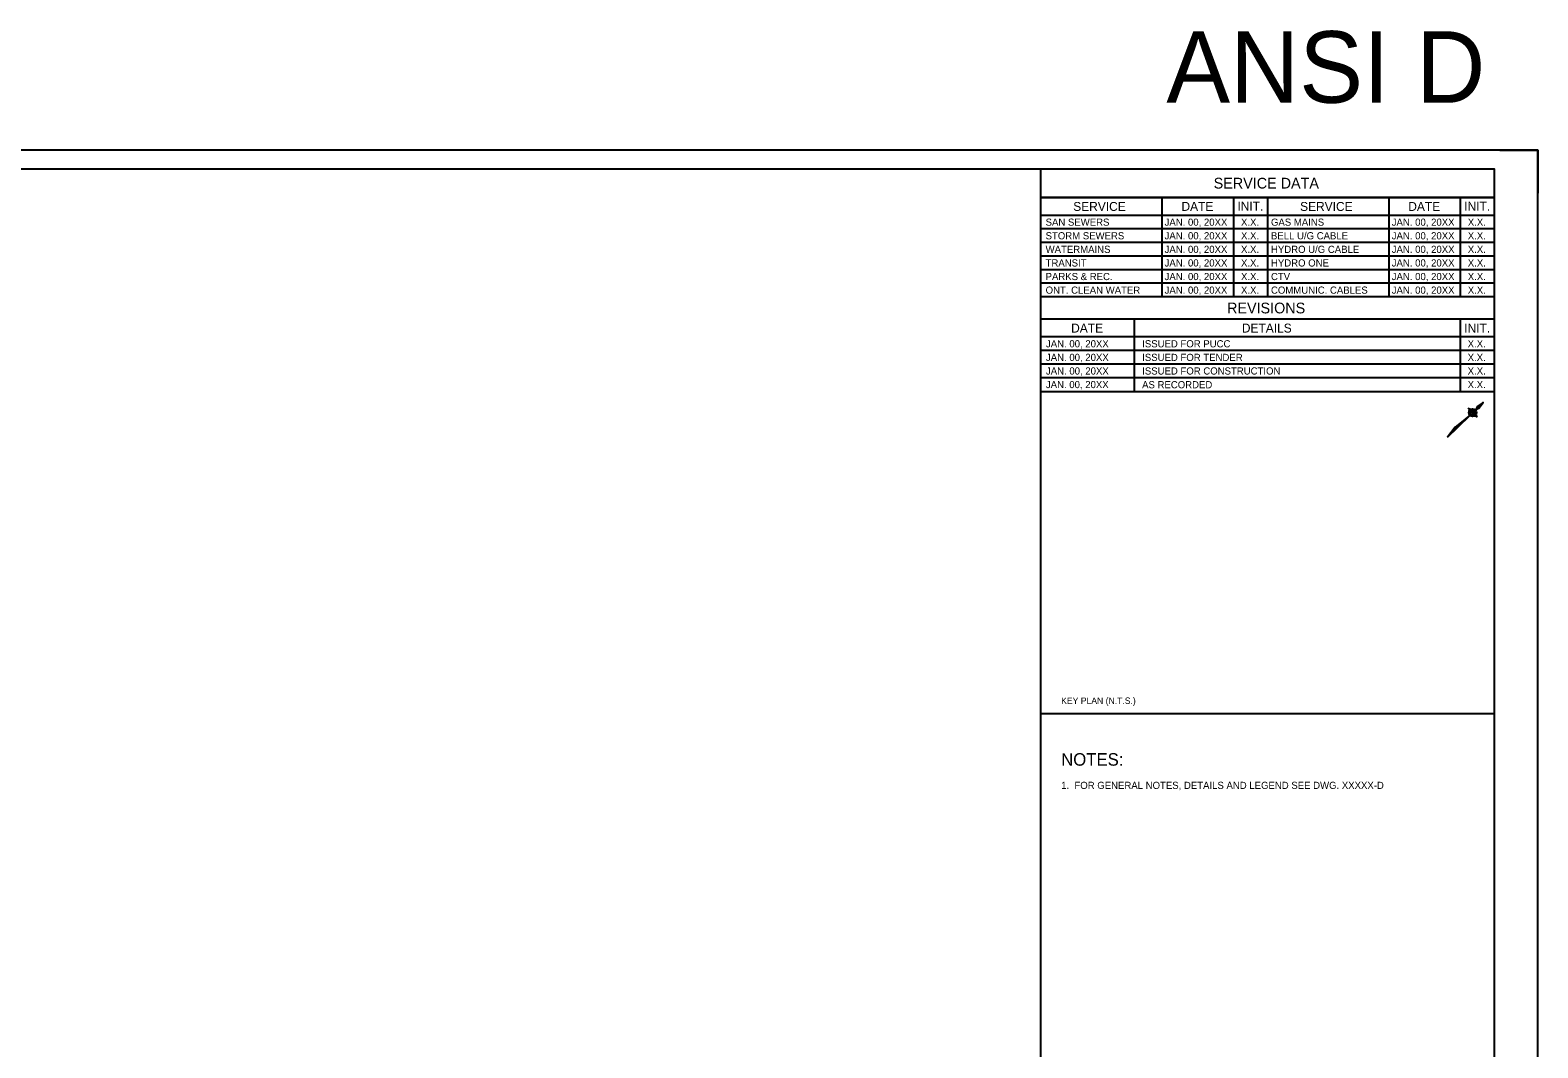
# Model space of a CAD drawing. Extents: x 613360 to 613780, y 4825621 to 4825911.
# Drawn here: x 613569.5 to 613780.3, y 4825769.2 to 4825911.5 of the extents above; entities that cross this region are included whole.
import ezdxf

# ---------------------------------------------------------------- set-up
doc = ezdxf.new("R2010")
doc.units = 0
for name, color, linetype in [('G-ANNO-KEYP', 7, 'Continuous'), ('G-ANNO-NPLT', 7, 'Continuous'), ('G-ANNO-TEXT', 7, 'Continuous'), ('G-ANNO-TTLB-TEXT', 7, 'Continuous'), ('G-TTLB-OTLN', 7, 'Continuous'), ('G-TTLB-OTLN-PB', 7, 'Continuous')]:
    doc.layers.add(name, color=color, linetype=linetype)

msp = doc.modelspace()

# ---------------------------------------------------------------- linework, layer by layer
at = {"layer": 'G-ANNO-KEYP'}
for p, q in [((613770.76, 4825857.62), (613767.64, 4825854.56)), ((613767.74, 4825854.69), (613770.74, 4825857.6)), ((613770.76, 4825857.62), (613768.73, 4825855.97)), ((613770.77, 4825858.38), (613770.51, 4825858.64)), ((613770.56, 4825858.46), (613770.71, 4825858.31)), ((613770.68, 4825858.07), (613770.78, 4825858.17)), ((613770.68, 4825858.05), (613770.76, 4825858.13)), ((613770.68, 4825858.03), (613770.76, 4825858.11)), ((613770.68, 4825858.01), (613770.75, 4825858.08)), ((613770.68, 4825857.99), (613770.74, 4825858.06)), ((613770.68, 4825857.97), (613770.74, 4825858.04)), ((613770.68, 4825857.96), (613770.74, 4825858.02)), ((613770.68, 4825857.94), (613770.74, 4825858)), ((613770.68, 4825857.92), (613770.74, 4825857.98)), ((613770.68, 4825857.91), (613770.74, 4825857.96)), ((613770.69, 4825858.59), (613770.84, 4825858.44)), ((613770.69, 4825858.12), (613770.85, 4825858.28)), ((613770.69, 4825858.1), (613770.8, 4825858.2)), ((613770.69, 4825857.89), (613770.74, 4825857.94)), ((613770.69, 4825857.87), (613770.75, 4825857.93)), ((613770.7, 4825858.15), (613771.01, 4825858.44)), ((613770.7, 4825857.86), (613770.75, 4825857.91)), ((613770.7, 4825857.85), (613770.75, 4825857.9)), ((613770.71, 4825858.18), (613770.97, 4825858.43)), ((613770.71, 4825857.83), (613770.76, 4825857.88)), ((613770.71, 4825857.82), (613770.76, 4825857.87)), ((613770.72, 4825857.8), (613770.77, 4825857.85)), ((613770.72, 4825857.79), (613770.77, 4825857.84)), ((613770.73, 4825858.21), (613770.94, 4825858.42)), ((613770.73, 4825857.78), (613770.78, 4825857.82)), ((613770.74, 4825857.77), (613770.78, 4825857.81)), ((613770.74, 4825857.75), (613770.79, 4825857.8)), ((613770.75, 4825857.74), (613770.8, 4825857.79)), ((613770.76, 4825858.26), (613770.89, 4825858.39)), ((613770.76, 4825857.73), (613770.8, 4825857.78)), ((613770.77, 4825857.72), (613770.81, 4825857.76)), ((613770.77, 4825857.71), (613770.82, 4825857.75)), ((613770.78, 4825857.7), (613770.83, 4825857.74)), ((613770.79, 4825857.69), (613770.84, 4825857.73)), ((613770.8, 4825857.68), (613770.85, 4825857.72)), ((613770.81, 4825857.67), (613770.86, 4825857.71)), ((613770.82, 4825857.66), (613770.86, 4825857.7)), ((613770.83, 4825857.65), (613770.87, 4825857.69)), ((613770.84, 4825857.64), (613770.88, 4825857.68)), ((613770.85, 4825857.63), (613770.9, 4825857.67)), ((613770.86, 4825857.62), (613770.91, 4825857.67)), ((613770.87, 4825858.3), (613771.03, 4825858.45)), ((613770.87, 4825858.3), (613771.03, 4825858.45)), ((613770.87, 4825857.61), (613770.92, 4825857.66)), ((613770.88, 4825857.61), (613770.93, 4825857.65)), ((613771.16, 4825858.25), (613770.89, 4825857.99)), ((613770.89, 4825857.99), (613770.92, 4825857.96)), ((613770.89, 4825857.6), (613770.94, 4825857.64)), ((613770.91, 4825857.59), (613770.95, 4825857.64)), ((613770.92, 4825857.96), (613771.11, 4825858.14)), ((613770.92, 4825857.58), (613770.97, 4825857.63)), ((613770.93, 4825857.58), (613770.98, 4825857.62)), ((613770.94, 4825857.57), (613770.99, 4825857.62)), ((613770.95, 4825858.35), (613771.06, 4825858.46)), ((613770.96, 4825857.56), (613771.01, 4825857.61)), ((613770.97, 4825857.56), (613771.02, 4825857.61)), ((613770.98, 4825857.55), (613771.04, 4825857.6)), ((613770.99, 4825858.37), (613771.08, 4825858.46)), ((613771, 4825857.55), (613771.05, 4825857.6)), ((613771.01, 4825857.54), (613771.07, 4825857.6)), ((613771.02, 4825858.38), (613771.1, 4825858.46)), ((613771.03, 4825857.54), (613771.08, 4825857.59)), ((613771.04, 4825857.54), (613771.1, 4825857.59)), ((613771.05, 4825858.39), (613771.12, 4825858.46)), ((613771.06, 4825857.53), (613771.12, 4825857.59)), ((613771.07, 4825858.39), (613771.14, 4825858.47)), ((613771.08, 4825857.53), (613771.14, 4825857.59)), ((613771.09, 4825857.53), (613771.16, 4825857.59)), ((613771.1, 4825858.4), (613771.16, 4825858.46)), ((613771.11, 4825858.14), (613771.12, 4825857.75)), ((613771.11, 4825857.53), (613771.18, 4825857.59)), ((613771.12, 4825858.4), (613771.18, 4825858.46)), ((613771.12, 4825857.75), (613771.39, 4825858.02)), ((613771.13, 4825857.53), (613771.2, 4825857.59)), ((613771.14, 4825858.4), (613771.2, 4825858.46)), ((613771.15, 4825857.52), (613771.22, 4825857.6)), ((613771.16, 4825858.4), (613771.22, 4825858.46)), ((613771.17, 4825857.87), (613771.16, 4825858.25)), ((613771.36, 4825858.05), (613771.17, 4825857.87)), ((613771.17, 4825857.53), (613771.25, 4825857.6)), ((613771.18, 4825858.4), (613771.23, 4825858.46)), ((613771.19, 4825858.4), (613771.25, 4825858.45)), ((613771.19, 4825857.53), (613771.28, 4825857.61)), ((613771.21, 4825858.4), (613771.27, 4825858.45)), ((613771.21, 4825857.53), (613771.31, 4825857.62)), ((613771.23, 4825858.39), (613771.28, 4825858.45)), ((613771.24, 4825858.39), (613771.3, 4825858.44)), ((613771.24, 4825857.53), (613771.35, 4825857.64)), ((613771.26, 4825858.39), (613771.31, 4825858.44)), ((613771.26, 4825857.54), (613771.6, 4825857.86)), ((613771.27, 4825858.38), (613771.32, 4825858.43)), ((613771.29, 4825858.38), (613771.34, 4825858.42)), ((613771.29, 4825857.55), (613771.59, 4825857.84)), ((613771.3, 4825858.37), (613771.35, 4825858.42)), ((613771.31, 4825858.37), (613771.36, 4825858.41)), ((613771.32, 4825857.56), (613771.58, 4825857.81)), ((613771.32, 4825857.56), (613771.58, 4825857.81)), ((613771.33, 4825858.36), (613771.38, 4825858.41)), ((613771.34, 4825858.35), (613771.39, 4825858.4)), ((613771.35, 4825858.35), (613771.4, 4825858.39)), ((613771.36, 4825858.34), (613771.41, 4825858.38)), ((613771.39, 4825858.02), (613771.36, 4825858.05)), ((613771.36, 4825857.58), (613771.56, 4825857.77)), ((613771.38, 4825858.33), (613771.42, 4825858.38)), ((613771.39, 4825858.32), (613771.43, 4825858.37)), ((613771.4, 4825858.31), (613771.44, 4825858.36)), ((613771.41, 4825858.31), (613771.45, 4825858.35)), ((613771.41, 4825857.6), (613771.53, 4825857.72)), ((613771.42, 4825858.3), (613771.46, 4825858.34)), ((613771.43, 4825858.29), (613771.47, 4825858.33)), ((613771.44, 4825858.28), (613771.48, 4825858.32)), ((613771.45, 4825858.27), (613771.49, 4825858.31)), ((613771.6, 4825857.4), (613771.45, 4825857.55)), ((613771.46, 4825858.26), (613771.5, 4825858.3)), ((613771.47, 4825858.25), (613771.51, 4825858.29)), ((613771.47, 4825858.24), (613771.52, 4825858.28)), ((613771.48, 4825858.22), (613771.53, 4825858.27)), ((613771.49, 4825858.21), (613771.54, 4825858.26)), ((613771.49, 4825857.78), (613771.6, 4825857.89)), ((613771.5, 4825858.2), (613771.54, 4825858.25)), ((613771.5, 4825858.19), (613771.55, 4825858.23)), ((613771.51, 4825858.18), (613771.56, 4825858.22)), ((613771.51, 4825857.82), (613771.61, 4825857.91)), ((613771.52, 4825858.16), (613771.56, 4825858.21)), ((613771.52, 4825858.15), (613771.57, 4825858.2)), ((613771.53, 4825858.14), (613771.58, 4825858.18)), ((613771.53, 4825858.12), (613771.58, 4825858.17)), ((613771.53, 4825857.85), (613771.61, 4825857.94)), ((613771.53, 4825857.61), (613771.78, 4825857.35)), ((613771.54, 4825858.11), (613771.59, 4825858.16)), ((613771.54, 4825858.09), (613771.59, 4825858.14)), ((613771.54, 4825858.08), (613771.6, 4825858.13)), ((613771.54, 4825857.91), (613771.62, 4825857.98)), ((613771.54, 4825857.88), (613771.61, 4825857.96)), ((613771.55, 4825858.06), (613771.6, 4825858.11)), ((613771.55, 4825858.05), (613771.6, 4825858.1)), ((613771.55, 4825858.03), (613771.61, 4825858.08)), ((613771.55, 4825858.01), (613771.61, 4825858.07)), ((613771.55, 4825857.99), (613771.61, 4825858.05)), ((613771.55, 4825857.97), (613771.61, 4825858.03)), ((613771.55, 4825857.95), (613771.62, 4825858.01)), ((613771.55, 4825857.93), (613771.62, 4825858)), ((613771.74, 4825857.53), (613771.59, 4825857.68)), ((613772.61, 4825859.43), (613771.63, 4825858.47)), ((613771.8, 4825858.85), (613771.63, 4825858.47)), ((613772.01, 4825858.63), (613771.63, 4825858.47)), ((613771.64, 4825858.47), (613772.57, 4825859.38)), ((613771.67, 4825858.49), (613772.52, 4825859.31)), ((613771.71, 4825858.5), (613772.47, 4825859.24)), ((613771.74, 4825858.51), (613772.42, 4825859.17)), ((613771.78, 4825858.53), (613772.37, 4825859.1)), ((613772.61, 4825859.43), (613771.8, 4825858.85)), ((613771.81, 4825858.54), (613772.32, 4825859.04)), ((613771.84, 4825858.56), (613772.27, 4825858.97)), ((613771.88, 4825858.57), (613772.22, 4825858.9)), ((613771.91, 4825858.59), (613772.16, 4825858.83)), ((613771.95, 4825858.6), (613772.11, 4825858.76)), ((613771.98, 4825858.61), (613772.06, 4825858.69)), ((613772.61, 4825859.43), (613772.01, 4825858.63)), ((613768.73, 4825855.97), (613767.64, 4825854.56)), ((613767.68, 4825854.61), (613769.09, 4825855.98)), ((613767.8, 4825854.77), (613770.62, 4825857.51)), ((613767.86, 4825854.84), (613770.5, 4825857.41)), ((613767.92, 4825854.92), (613770.39, 4825857.31)), ((613767.98, 4825854.99), (613770.27, 4825857.22)), ((613768.04, 4825855.07), (613770.15, 4825857.12)), ((613768.1, 4825855.15), (613770.03, 4825857.02)), ((613768.15, 4825855.22), (613769.91, 4825856.92)), ((613768.21, 4825855.3), (613769.79, 4825856.83)), ((613768.27, 4825855.37), (613769.67, 4825856.73)), ((613768.33, 4825855.45), (613769.55, 4825856.63)), ((613768.39, 4825855.53), (613769.43, 4825856.54)), ((613768.45, 4825855.6), (613769.31, 4825856.44)), ((613768.51, 4825855.68), (613769.19, 4825856.34)), ((613768.57, 4825855.75), (613769.07, 4825856.25)), ((613768.62, 4825855.83), (613768.95, 4825856.15)), ((613768.68, 4825855.91), (613768.83, 4825856.05))]:
    msp.add_line(p, q, dxfattribs=at)
for points in [[(613767.64, 4825854.56), (613770.76, 4825857.62), (613768.73, 4825855.97)], [(613771.63, 4825858.47), (613772.01, 4825858.63), (613772.61, 4825859.43)]]:
    msp.add_lwpolyline(points, close=True, dxfattribs=at)
for radius in [0.541, 0.47, 0.407, 0.348]:
    msp.add_circle((613771.15, 4825858), radius, dxfattribs=at)
at = {"layer": 'G-TTLB-OTLN'}
for p, q in [((613710.78, 4825860.98), (613710.78, 4825892.08)), ((613774.18, 4825888.08), (613710.78, 4825888.08)), ((613710.78, 4825888.08), (613774.18, 4825888.08)), ((613727.73, 4825888.08), (613727.73, 4825874.18)), ((613737.73, 4825888.08), (613737.73, 4825874.18)), ((613742.48, 4825888.08), (613742.48, 4825874.18)), ((613759.43, 4825888.08), (613759.43, 4825874.18)), ((613769.43, 4825888.08), (613769.43, 4825874.18)), ((613774.18, 4825885.58), (613710.78, 4825885.58)), ((613774.18, 4825883.68), (613710.78, 4825883.68)), ((613774.18, 4825881.78), (613710.78, 4825881.78)), ((613774.18, 4825879.88), (613710.78, 4825879.88)), ((613774.18, 4825877.98), (613710.78, 4825877.98)), ((613774.18, 4825876.08), (613710.78, 4825876.08)), ((613774.18, 4825874.18), (613710.78, 4825874.18)), ((613774.18, 4825871.08), (613710.78, 4825871.08)), ((613723.83, 4825871.08), (613723.83, 4825860.98)), ((613769.43, 4825871.08), (613769.43, 4825860.98)), ((613774.18, 4825868.58), (613710.78, 4825868.58)), ((613774.18, 4825866.68), (613710.78, 4825866.68)), ((613774.18, 4825864.78), (613710.78, 4825864.78)), ((613774.18, 4825862.88), (613710.78, 4825862.88)), ((613710.78, 4825623.51), (613710.78, 4825815.93))]:
    msp.add_line(p, q, dxfattribs=at)
for points in [[(613380.09, 4825892.08), (613774.18, 4825892.08), (613774.18, 4825623.51), (613380.09, 4825623.51)], [(613710.78, 4825860.98), (613774.18, 4825860.98), (613774.18, 4825815.93), (613710.78, 4825815.93)]]:
    msp.add_lwpolyline(points, close=True, dxfattribs=at)
at = {"layer": 'G-TTLB-OTLN-PB'}
for p, q in [((613774.98, 4825894.68), (613780.27, 4825894.68)), ((613780.27, 4825894.68), (613780.27, 4825888.68))]:
    msp.add_line(p, q, dxfattribs=at)
msp.add_lwpolyline([(613359.58, 4825620.91), (613780.27, 4825620.91), (613780.27, 4825894.68), (613359.58, 4825894.68)], close=True, dxfattribs=at)

# ---------------------------------------------------------------- texts
at = {"layer": 'G-ANNO-KEYP'}
msp.add_text('KEY PLAN (N.T.S.)', height=0.9, rotation=359.9998, dxfattribs=at).set_placement((613713.64, 4825817.29))
at = {"layer": 'G-ANNO-NPLT'}
msp.add_text('ANSI D', height=10, dxfattribs=at).set_placement((613728.34, 4825901.32))
at = {"layer": 'G-ANNO-TEXT'}
for s, height, p in [('NOTES:', 1.75, (613713.64, 4825808.66)), ('1.  FOR GENERAL NOTES, DETAILS AND LEGEND SEE DWG. XXXXX-D', 1, (613713.64, 4825805.41))]:
    msp.add_text(s, height=height, rotation=0.0057, dxfattribs=at).set_placement(p)
at = {"layer": 'G-ANNO-TTLB-TEXT'}
for s, height, p in [('SERVICE DATA', 1.5, (613734.96, 4825889.33)), ('SERVICE', 1.25, (613715.33, 4825886.2)), ('DATE', 1.25, (613730.46, 4825886.21)), ('INIT.', 1.25, (613738.28, 4825886.24)), ('SERVICE', 1.25, (613747.04, 4825886.2)), ('DATE', 1.25, (613762.16, 4825886.2)), ('INIT.', 1.25, (613769.98, 4825886.24)), ('SAN SEWERS', 1, (613711.47, 4825884.13)), ('GAS MAINS', 1, (613742.97, 4825884.13)), ('STORM SEWERS', 1, (613711.47, 4825882.23)), ('BELL U/G CABLE', 1, (613742.97, 4825882.23)), ('WATERMAINS', 1, (613711.47, 4825880.33)), ('HYDRO U/G CABLE', 1, (613742.97, 4825880.33)), ('TRANSIT', 1, (613711.47, 4825878.43)), ('HYDRO ONE', 1, (613742.97, 4825878.43)), ('PARKS & REC.', 1, (613711.47, 4825876.53)), ('CTV', 1, (613742.97, 4825876.53)), ('ONT. CLEAN WATER ', 1, (613711.47, 4825874.63)), ('COMMUNIC. CABLES', 1, (613742.97, 4825874.63)), ('REVISIONS', 1.5, (613736.83, 4825871.88)), ('DATE', 1.25, (613715.04, 4825869.2)), ('DETAILS', 1.25, (613738.9, 4825869.2)), ('INIT.', 1.25, (613769.98, 4825869.2)), ('JAN. 00, 20XX', 1, (613711.52, 4825863.33)), ('JAN. 00, 20XX', 1, (613711.51, 4825861.43))]:
    msp.add_text(s, height=height, dxfattribs=at).set_placement(p)
for s, p in [('JAN. 00, 20XX', (613728.1, 4825884.13)), ('X.X.', (613738.78, 4825884.13)), ('JAN. 00, 20XX', (613759.85, 4825884.13)), ('X.X.', (613770.48, 4825884.13)), ('JAN. 00, 20XX', (613728.1, 4825882.23)), ('X.X.', (613738.78, 4825882.23)), ('JAN. 00, 20XX', (613759.85, 4825882.23)), ('X.X.', (613770.48, 4825882.23)), ('JAN. 00, 20XX', (613728.1, 4825880.33)), ('X.X.', (613738.78, 4825880.33)), ('JAN. 00, 20XX', (613759.85, 4825880.33)), ('X.X.', (613770.48, 4825880.33)), ('JAN. 00, 20XX', (613728.1, 4825878.43)), ('X.X.', (613738.78, 4825878.43)), ('JAN. 00, 20XX', (613759.85, 4825878.43)), ('X.X.', (613770.48, 4825878.43)), ('JAN. 00, 20XX', (613728.1, 4825876.53)), ('X.X.', (613738.78, 4825876.53)), ('JAN. 00, 20XX', (613759.85, 4825876.53)), ('X.X.', (613770.48, 4825876.53)), ('JAN. 00, 20XX', (613728.1, 4825874.63)), ('X.X.', (613738.78, 4825874.63)), ('JAN. 00, 20XX', (613759.85, 4825874.63)), ('X.X.', (613770.48, 4825874.63)), ('JAN. 00, 20XX', (613711.52, 4825867.13)), ('ISSUED FOR PUCC', (613724.97, 4825867.13)), ('X.X.', (613770.46, 4825867.13)), ('JAN. 00, 20XX', (613711.52, 4825865.23)), ('ISSUED FOR TENDER', (613724.97, 4825865.23)), ('X.X.', (613770.46, 4825865.23)), ('ISSUED FOR CONSTRUCTION', (613724.97, 4825863.33)), ('X.X.', (613770.46, 4825863.33)), ('AS RECORDED', (613724.96, 4825861.41)), ('X.X.', (613770.46, 4825861.43))]:
    msp.add_text(s, height=1, rotation=360, dxfattribs=at).set_placement(p)

doc.saveas('drawing.dxf')
